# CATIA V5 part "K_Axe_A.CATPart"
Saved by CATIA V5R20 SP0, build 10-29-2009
Part number: Axe_A
Bounding box of the stored display mesh (mm): x -10 to 10, y -10 to 10, z 0 to 86
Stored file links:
  G:\Khaled_CFAO_2011\ST2M\ST2M_GR2\echouteau\Khaled\CAD_ThinkMotion\K_Axe_A.CATPart
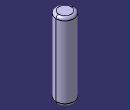
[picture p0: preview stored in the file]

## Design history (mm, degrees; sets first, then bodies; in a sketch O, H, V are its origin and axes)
AxisSystem1: origin (0, 0, 0), X (1, 0, 0), Y (0, 1, 0), Z (0, 0, 1)
Body1 (main body)
  Sketch1 on xy-plane, origin (0, 0, 0), H (1, 0, 0), V (0, 1, 0)
    circle A1 centre (0, 0) radius 10
    radius A1 = 10
  Pad1: profile Sketch1, direction (0, 0, 1), length 86
  Fillet1: radius 3, on end face of Pad1
  Fillet2: radius 3, on face of Pad1 from Sketch1.A1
